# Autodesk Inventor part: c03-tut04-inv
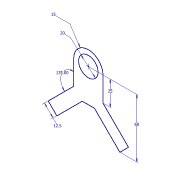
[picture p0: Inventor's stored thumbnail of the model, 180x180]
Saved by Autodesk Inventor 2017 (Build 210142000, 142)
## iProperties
Created: 2010-01
Part Number: c03-tut04-inv
Document SubType Name: Modeling
Designer: CADSoft
Density: 1 g/cm^3
Material: Generic
Appearance: Default
Author: CADSoft
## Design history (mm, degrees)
sketch "Sketch1"
  geometry: L1 (-41.161, -51.161)-(-32.322, -60); L2 (-32.322, -60)-(-6.25, -33.928); L3 (-6.25, -33.928)-(6.25, -33.928); L4 (6.25, -33.928)-(32.322, -60); L5 (32.322, -60)-(41.161, -51.161); L6 (41.161, -51.161)-(15, -25); L7 (15, -25)-(15, 0); L8 (-15, 0)-(-15, -25); L9 (-15, -25)-(-41.161, -51.161); C1 r 10 at (0, 0); A1 r 15 centre (0, 0) between (15, 0) and (-15, 0); 2 further points
  constraints: 18 end point, 5 equal length, 3 coincident, 3 parallel, 2 centre point, 2 perpendicular, 2 point on circle, 2 tangent, 1 horizontal, 1 vertical, 1 other
  dimensions: "d0" = 25 distance of L8.start L8.end; "d1" = 60 vertical distance of L1.end A1.centre; "d2" = 12.5 distance of L4.end L5.end; "d3" = 135 deg angle of L6 L7; "d4" = 15 radius of A1; "d5" = 20 diameter of C1
